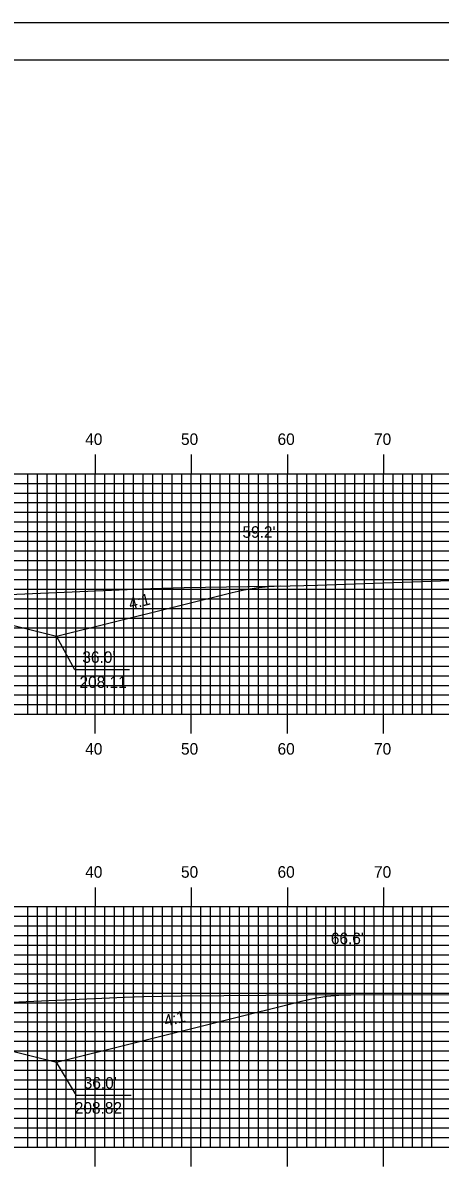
# Model space of a CAD drawing. Extents: x 1821211 to 1821555, y 442591 to 442811.
# Drawn here: x 1821409.7 to 1821453.1, y 442691.2 to 442810.5 of the extents above; entities that cross this region are included whole.
import ezdxf

# ---------------------------------------------------------------- set-up
doc = ezdxf.new("R2010")
doc.units = 0
for name, color, linetype in [('ANNOTATION', 7, 'Continuous'), ('BORDER', 7, 'Continuous'), ('D_Roadway_SlopeLines', 7, 'Continuous'), ('D_Text_Standard', 7, 'Continuous'), ('H_V ANNOTATION', 7, 'Continuous'), ('MAJOR', 7, 'Continuous'), ('MINOR', 7, 'Continuous'), ('PLOT BOUNDARY', 7, 'Continuous'), ('S_Roadway_Centerline', 7, 'Continuous')]:
    doc.layers.add(name, color=color, linetype=linetype)

msp = doc.modelspace()

# ---------------------------------------------------------------- linework, layer by layer
at = {"layer": 'ANNOTATION'}
for points in [[(1821420.82, 442743.28), (1821415.12, 442743.28), (1821413.23, 442746.78)], [(1821420.97, 442699.01), (1821415.28, 442699.01), (1821413.23, 442702.49)]]:
    msp.add_lwpolyline(points, dxfattribs=at)
at = {"layer": 'BORDER'}
msp.add_lwpolyline([(1821227.63, 442596.67), (1821547.63, 442596.67), (1821547.63, 442806.67), (1821227.63, 442806.67)], close=True, dxfattribs=at)
at = {"layer": 'D_Roadway_SlopeLines'}
for points in [[(1821413.23, 442746.78), (1821431.48, 442751.34), (1821432.73, 442751.62), (1821433.98, 442751.82), (1821435.23, 442751.95), (1821436.48, 442752.01)], [(1821399.23, 442750.28), (1821413.23, 442746.78)], [(1821413.23, 442702.49), (1821438.81, 442708.88), (1821440.06, 442709.16), (1821441.31, 442709.35), (1821442.56, 442709.47), (1821443.81, 442709.51)], [(1821399.23, 442705.99), (1821413.23, 442702.49)]]:
    msp.add_lwpolyline(points, dxfattribs=at)
at = {"layer": 'MAJOR'}
for p, q in [((1821417.23, 442765.67), (1821417.23, 442763.67)), ((1821427.23, 442765.67), (1821427.23, 442763.67)), ((1821437.23, 442765.67), (1821437.23, 442763.67)), ((1821447.23, 442765.67), (1821447.23, 442763.67)), ((1821237.23, 442763.67), (1821517.23, 442763.67)), ((1821237.23, 442763.67), (1821517.23, 442763.67)), ((1821417.23, 442738.67), (1821417.23, 442763.67)), ((1821427.23, 442738.67), (1821427.23, 442763.67)), ((1821437.23, 442738.67), (1821437.23, 442763.67)), ((1821447.23, 442738.67), (1821447.23, 442763.67)), ((1821237.23, 442758.67), (1821517.23, 442758.67)), ((1821237.23, 442753.67), (1821517.23, 442753.67)), ((1821237.23, 442748.67), (1821517.23, 442748.67)), ((1821237.23, 442743.67), (1821517.23, 442743.67)), ((1821237.23, 442738.67), (1821517.23, 442738.67)), ((1821237.23, 442738.67), (1821517.23, 442738.67)), ((1821417.23, 442736.66), (1821417.23, 442738.67)), ((1821427.23, 442736.66), (1821427.23, 442738.67)), ((1821437.23, 442736.66), (1821437.23, 442738.67)), ((1821447.23, 442736.66), (1821447.23, 442738.67)), ((1821417.23, 442720.67), (1821417.23, 442718.67)), ((1821427.23, 442720.67), (1821427.23, 442718.67)), ((1821437.23, 442720.67), (1821437.23, 442718.67)), ((1821447.23, 442720.67), (1821447.23, 442718.67)), ((1821237.23, 442718.67), (1821517.23, 442718.67)), ((1821237.23, 442718.67), (1821517.23, 442718.67)), ((1821417.23, 442693.67), (1821417.23, 442718.67)), ((1821427.23, 442693.67), (1821427.23, 442718.67)), ((1821437.23, 442693.67), (1821437.23, 442718.67)), ((1821447.23, 442693.67), (1821447.23, 442718.67)), ((1821237.23, 442713.67), (1821517.23, 442713.67)), ((1821237.23, 442708.67), (1821517.23, 442708.67)), ((1821237.23, 442703.67), (1821517.23, 442703.67)), ((1821237.23, 442698.67), (1821517.23, 442698.67)), ((1821237.23, 442693.67), (1821517.23, 442693.67)), ((1821237.23, 442693.67), (1821517.23, 442693.67)), ((1821417.23, 442691.66), (1821417.23, 442693.67)), ((1821427.23, 442691.66), (1821427.23, 442693.67)), ((1821437.23, 442691.66), (1821437.23, 442693.67)), ((1821447.23, 442691.66), (1821447.23, 442693.67))]:
    msp.add_line(p, q, dxfattribs=at)
at = {"layer": 'MINOR'}
for p, q in [((1821410.23, 442738.67), (1821410.23, 442763.67)), ((1821411.23, 442738.67), (1821411.23, 442763.67)), ((1821412.23, 442738.67), (1821412.23, 442763.67)), ((1821413.23, 442738.67), (1821413.23, 442763.67)), ((1821414.23, 442738.67), (1821414.23, 442763.67)), ((1821415.23, 442738.67), (1821415.23, 442763.67)), ((1821416.23, 442738.67), (1821416.23, 442763.67)), ((1821418.23, 442738.67), (1821418.23, 442763.67)), ((1821419.23, 442738.67), (1821419.23, 442763.67)), ((1821420.23, 442738.67), (1821420.23, 442763.67)), ((1821421.23, 442738.67), (1821421.23, 442763.67)), ((1821422.23, 442738.67), (1821422.23, 442763.67)), ((1821423.23, 442738.67), (1821423.23, 442763.67)), ((1821424.23, 442738.67), (1821424.23, 442763.67)), ((1821425.23, 442738.67), (1821425.23, 442763.67)), ((1821426.23, 442738.67), (1821426.23, 442763.67)), ((1821428.23, 442738.67), (1821428.23, 442763.67)), ((1821429.23, 442738.67), (1821429.23, 442763.67)), ((1821430.23, 442738.67), (1821430.23, 442763.67)), ((1821431.23, 442738.67), (1821431.23, 442763.67)), ((1821432.23, 442738.67), (1821432.23, 442763.67)), ((1821433.23, 442738.67), (1821433.23, 442763.67)), ((1821434.23, 442738.67), (1821434.23, 442763.67)), ((1821435.23, 442738.67), (1821435.23, 442763.67)), ((1821436.23, 442738.67), (1821436.23, 442763.67)), ((1821438.23, 442738.67), (1821438.23, 442763.67)), ((1821439.23, 442738.67), (1821439.23, 442763.67)), ((1821440.23, 442738.67), (1821440.23, 442763.67)), ((1821441.23, 442738.67), (1821441.23, 442763.67)), ((1821442.23, 442738.67), (1821442.23, 442763.67)), ((1821443.23, 442738.67), (1821443.23, 442763.67)), ((1821444.23, 442738.67), (1821444.23, 442763.67)), ((1821445.23, 442738.67), (1821445.23, 442763.67)), ((1821446.23, 442738.67), (1821446.23, 442763.67)), ((1821448.23, 442738.67), (1821448.23, 442763.67)), ((1821449.23, 442738.67), (1821449.23, 442763.67)), ((1821450.23, 442738.67), (1821450.23, 442763.67)), ((1821451.23, 442738.67), (1821451.23, 442763.67)), ((1821452.23, 442738.67), (1821452.23, 442763.67)), ((1821237.23, 442762.67), (1821517.23, 442762.67)), ((1821237.23, 442761.67), (1821517.23, 442761.67)), ((1821237.23, 442760.67), (1821517.23, 442760.67)), ((1821237.23, 442759.67), (1821517.23, 442759.67)), ((1821237.23, 442757.67), (1821517.23, 442757.67)), ((1821237.23, 442756.67), (1821517.23, 442756.67)), ((1821237.23, 442755.67), (1821517.23, 442755.67)), ((1821237.23, 442754.67), (1821517.23, 442754.67)), ((1821237.23, 442752.67), (1821517.23, 442752.67)), ((1821237.23, 442751.67), (1821517.23, 442751.67)), ((1821237.23, 442750.67), (1821517.23, 442750.67)), ((1821237.23, 442749.67), (1821517.23, 442749.67)), ((1821237.23, 442747.67), (1821517.23, 442747.67)), ((1821237.23, 442746.67), (1821517.23, 442746.67)), ((1821237.23, 442745.67), (1821517.23, 442745.67)), ((1821237.23, 442744.67), (1821517.23, 442744.67)), ((1821237.23, 442742.67), (1821517.23, 442742.67)), ((1821237.23, 442741.67), (1821517.23, 442741.67)), ((1821237.23, 442740.67), (1821517.23, 442740.67)), ((1821237.23, 442739.67), (1821517.23, 442739.67)), ((1821410.23, 442693.67), (1821410.23, 442718.67)), ((1821411.23, 442693.67), (1821411.23, 442718.67)), ((1821412.23, 442693.67), (1821412.23, 442718.67)), ((1821413.23, 442693.67), (1821413.23, 442718.67)), ((1821414.23, 442693.67), (1821414.23, 442718.67)), ((1821415.23, 442693.67), (1821415.23, 442718.67)), ((1821416.23, 442693.67), (1821416.23, 442718.67)), ((1821418.23, 442693.67), (1821418.23, 442718.67)), ((1821419.23, 442693.67), (1821419.23, 442718.67)), ((1821420.23, 442693.67), (1821420.23, 442718.67)), ((1821421.23, 442693.67), (1821421.23, 442718.67)), ((1821422.23, 442693.67), (1821422.23, 442718.67)), ((1821423.23, 442693.67), (1821423.23, 442718.67)), ((1821424.23, 442693.67), (1821424.23, 442718.67)), ((1821425.23, 442693.67), (1821425.23, 442718.67)), ((1821426.23, 442693.67), (1821426.23, 442718.67)), ((1821428.23, 442693.67), (1821428.23, 442718.67)), ((1821429.23, 442693.67), (1821429.23, 442718.67)), ((1821430.23, 442693.67), (1821430.23, 442718.67)), ((1821431.23, 442693.67), (1821431.23, 442718.67)), ((1821432.23, 442693.67), (1821432.23, 442718.67)), ((1821433.23, 442693.67), (1821433.23, 442718.67)), ((1821434.23, 442693.67), (1821434.23, 442718.67)), ((1821435.23, 442693.67), (1821435.23, 442718.67)), ((1821436.23, 442693.67), (1821436.23, 442718.67)), ((1821438.23, 442693.67), (1821438.23, 442718.67)), ((1821439.23, 442693.67), (1821439.23, 442718.67)), ((1821440.23, 442693.67), (1821440.23, 442718.67)), ((1821441.23, 442693.67), (1821441.23, 442718.67)), ((1821442.23, 442693.67), (1821442.23, 442718.67)), ((1821443.23, 442693.67), (1821443.23, 442718.67)), ((1821444.23, 442693.67), (1821444.23, 442718.67)), ((1821445.23, 442693.67), (1821445.23, 442718.67)), ((1821446.23, 442693.67), (1821446.23, 442718.67)), ((1821448.23, 442693.67), (1821448.23, 442718.67)), ((1821449.23, 442693.67), (1821449.23, 442718.67)), ((1821450.23, 442693.67), (1821450.23, 442718.67)), ((1821451.23, 442693.67), (1821451.23, 442718.67)), ((1821452.23, 442693.67), (1821452.23, 442718.67)), ((1821237.23, 442717.67), (1821517.23, 442717.67)), ((1821237.23, 442716.67), (1821517.23, 442716.67)), ((1821237.23, 442715.67), (1821517.23, 442715.67)), ((1821237.23, 442714.67), (1821517.23, 442714.67)), ((1821237.23, 442712.67), (1821517.23, 442712.67)), ((1821237.23, 442711.67), (1821517.23, 442711.67)), ((1821237.23, 442710.67), (1821517.23, 442710.67)), ((1821237.23, 442709.67), (1821517.23, 442709.67)), ((1821237.23, 442707.67), (1821517.23, 442707.67)), ((1821237.23, 442706.67), (1821517.23, 442706.67)), ((1821237.23, 442705.67), (1821517.23, 442705.67)), ((1821237.23, 442704.67), (1821517.23, 442704.67)), ((1821237.23, 442702.67), (1821517.23, 442702.67)), ((1821237.23, 442701.67), (1821517.23, 442701.67)), ((1821237.23, 442700.67), (1821517.23, 442700.67)), ((1821237.23, 442699.67), (1821517.23, 442699.67)), ((1821237.23, 442697.67), (1821517.23, 442697.67)), ((1821237.23, 442696.67), (1821517.23, 442696.67)), ((1821237.23, 442695.67), (1821517.23, 442695.67)), ((1821237.23, 442694.67), (1821517.23, 442694.67))]:
    msp.add_line(p, q, dxfattribs=at)
at = {"layer": 'PLOT BOUNDARY'}
msp.add_lwpolyline([(1821211.44, 442590.55), (1821551.44, 442590.55), (1821551.44, 442810.55), (1821211.44, 442810.55)], close=True, dxfattribs=at)
at = {"layer": 'S_Roadway_Centerline'}
for points in [[(1821325.17, 442749.23), (1821329.44, 442749.38), (1821340.71, 442749.42), (1821346.79, 442749.38), (1821362.22, 442749.65), (1821375.53, 442750.38), (1821379.82, 442750.56), (1821388.78, 442750.62), (1821409.08, 442751.15), (1821423.03, 442751.75), (1821426.49, 442751.84), (1821437.52, 442752.03), (1821440.35, 442752.09), (1821460.04, 442752.79), (1821486.75, 442753.64), (1821493.96, 442753.73), (1821498.54, 442753.82), (1821510.55, 442754.43), (1821517.23, 442754.51)], [(1821237.23, 442703.27), (1821237.53, 442703.28), (1821264.33, 442703.79), (1821303.65, 442705.19), (1821311.23, 442705.53), (1821321.49, 442705.86), (1821351.91, 442706.32), (1821353.94, 442706.35), (1821354.59, 442706.37), (1821355.88, 442706.42), (1821388.83, 442707.87), (1821420.29, 442709.25), (1821422.31, 442709.32), (1821426.24, 442709.4), (1821439.35, 442709.51), (1821465.23, 442709.52), (1821471.24, 442709.51), (1821476.19, 442709.63), (1821481.91, 442709.95), (1821490.45, 442710.34), (1821494.15, 442710.38), (1821514.65, 442710.89), (1821517.23, 442710.91)]]:
    msp.add_lwpolyline(points, dxfattribs=at)

# ---------------------------------------------------------------- texts
at = {"layer": 'ANNOTATION'}
for p in [(1821420.89, 442749.56), (1821424.56, 442706.18)]:
    msp.add_text('4:1', height=1.2, rotation=14.0362, dxfattribs=at).set_placement(p)
for s, p in [("36.0'", (1821415.9, 442744.01)), ('208.11', (1821415.61, 442741.41)), ("36.0'", (1821416.05, 442699.74)), ('208.82', (1821415.12, 442697.14))]:
    msp.add_text(s, height=1.2, dxfattribs=at).set_placement(p)
at = {"layer": 'D_Text_Standard'}
for s, p in [("59.2'", (1821432.55, 442757.02)), ("66.6'", (1821441.74, 442714.76))]:
    msp.add_text(s, height=1.2, dxfattribs=at).set_placement(p)
at = {"layer": 'H_V ANNOTATION'}
for s, p in [('40', (1821416.2, 442766.67)), ('50', (1821426.16, 442766.67)), ('60', (1821436.2, 442766.67)), ('70', (1821446.23, 442766.67)), ('40', (1821416.2, 442734.47)), ('50', (1821426.16, 442734.47)), ('60', (1821436.2, 442734.47)), ('70', (1821446.23, 442734.47)), ('40', (1821416.2, 442721.67)), ('50', (1821426.16, 442721.67)), ('60', (1821436.2, 442721.67)), ('70', (1821446.23, 442721.67))]:
    msp.add_text(s, height=1.2, dxfattribs=at).set_placement(p)

doc.saveas('drawing.dxf')
